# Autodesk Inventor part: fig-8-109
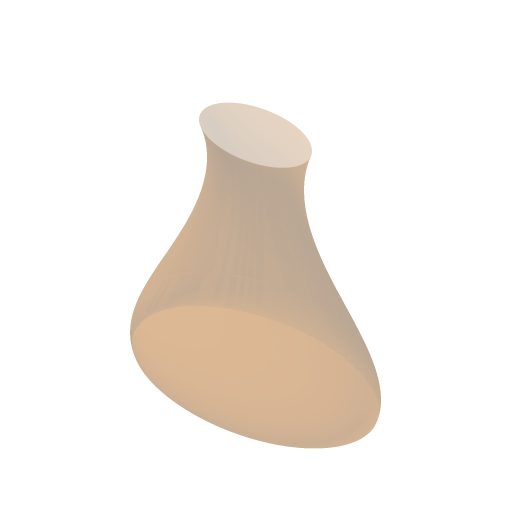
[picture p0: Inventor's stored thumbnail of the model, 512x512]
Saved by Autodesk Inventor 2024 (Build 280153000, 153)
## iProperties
Created: 2004-05
Part Number: fig-8-109
Document SubType Name: Modeling
Designer: CADCIM Technologies
Manufacturer: Standard
Standards Organization: Custom
Density: 1 g/cm^3
Material: Generic
Appearance: Default
Author: CADCIM Technologies
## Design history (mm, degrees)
sketch "Sketch4"
  geometry: 1 further point; 1 other entity
  constraints: 2 other
workplane "Work Plane2"
sketch "Sketch5"
  geometry: 1 further point; 1 other entity
  constraints: 2 other
feature "LoftSrf1" sketch "Sketch5" dims "d4" = 20, "d5" = 110 deg, "d6" = 40, "d7" = 70 deg
patch "Boundary Patch1" dims "d8" = 0, "d9" = 0
body "Srf1"
body "Srf2"
other parameters: "d3" = 33.5
